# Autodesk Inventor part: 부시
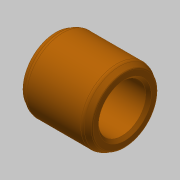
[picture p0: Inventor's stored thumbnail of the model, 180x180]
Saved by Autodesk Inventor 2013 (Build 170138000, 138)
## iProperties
Created: 2018-11
Part Number: 부시
Material: 강철, 연강
Document SubType Name: Modeling
Designer: mduedu
Density: 1 g/cm^3
Author: mduedu
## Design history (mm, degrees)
sketch "스케치1"
  geometry: C1 r 8.5 at (0, 0); C2 r 13 at (0, 0); 1 further point
  constraints: 2 centre point, 2 coincident
  dimensions: "d0" = 17 diameter of C1; "d1" = 26 diameter of C2
extrude "돌출1" new body sketch "스케치1" distance "d2" = 25; taper "d3" = 0 deg
chamfer "모따기4" distance "d14" = 1; stored, may be unused: second distance "d15" = 2, angle "d16" = 15 deg
chamfer "모따기5" distance "d17" = 2.3; stored, may be unused: second distance "d18" = 2, angle "d19" = 30 deg
chamfer "모따기6" distance "d20" = 2.3; stored, may be unused: second distance "d21" = 2, angle "d22" = 30 deg
fillet "모깎기2" dims "d23" = 2, "d24" = 0.5
fillet "모깎기3" dims "d25" = 2, "d26" = 0.5
node "솔리드1"
